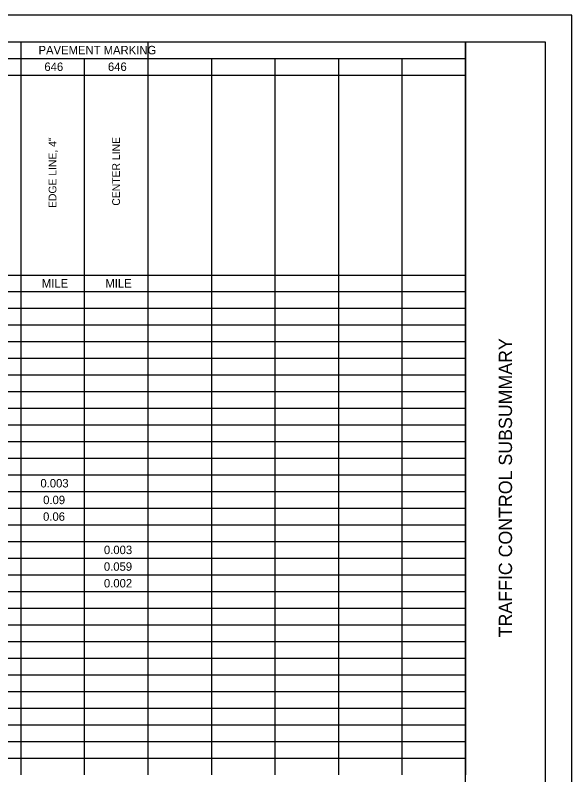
# Model space of a CAD drawing. Extents: x 0 to 34, y 0 to 22.
# Drawn here: x 23.52 to 34, y 7.71 to 22 of the extents above; entities that cross this region are included whole.
import ezdxf

# ---------------------------------------------------------------- set-up
doc = ezdxf.new("R2010")
doc.units = 0
for name, color, linetype in [('SH_Border', 7, 'Continuous'), ('SH_Cut_Line', 7, 'Continuous'), ('SH_Data', 7, 'Continuous'), ('SH_Text', 7, 'Continuous')]:
    doc.layers.add(name, color=color, linetype=linetype)

msp = doc.modelspace()

# ---------------------------------------------------------------- linework, layer by layer
at = {"layer": 'SH_Border'}
msp.add_line((32, 0.5), (32, 21.5), dxfattribs=at)
msp.add_lwpolyline([(1.5, 21.5), (33.5, 21.5), (33.5, 0.5), (1.5, 0.5)], close=True, dxfattribs=at)
at = {"layer": 'SH_Cut_Line'}
msp.add_lwpolyline([(0, 0), (34, 0), (34, 22), (0, 22)], close=True, dxfattribs=at)
at = {"layer": 'SH_Text'}
for p, q in [((16.454, 21.5), (23.629, 21.5)), ((23.629, 21.5), (24.825, 21.5)), ((23.629, 21.5), (23.629, 21.187)), ((24.825, 21.5), (26.021, 21.5)), ((26.021, 21.5), (28.413, 21.5)), ((26.021, 21.5), (26.021, 21.187)), ((28.413, 21.5), (30.804, 21.5)), ((30.804, 21.5), (32, 21.5)), ((32, 21.5), (32, 21.187)), ((16.454, 21.187), (23.629, 21.187)), ((23.629, 21.187), (24.825, 21.187)), ((23.629, 21.187), (23.629, 20.873)), ((24.825, 21.187), (26.021, 21.187)), ((24.825, 21.187), (24.825, 20.873)), ((26.021, 21.187), (28.413, 21.187)), ((26.021, 21.187), (26.021, 20.873)), ((27.217, 21.187), (27.217, 20.873)), ((28.413, 21.187), (30.804, 21.187)), ((28.413, 21.187), (28.413, 20.873)), ((29.608, 21.187), (29.608, 20.873)), ((30.804, 21.187), (32, 21.187)), ((30.804, 21.187), (30.804, 20.873)), ((32, 21.187), (32, 20.873)), ((16.454, 20.873), (23.629, 20.873)), ((23.629, 20.873), (24.825, 20.873)), ((23.629, 20.873), (23.629, 20.56)), ((24.825, 20.873), (26.021, 20.873)), ((24.825, 20.873), (24.825, 20.56)), ((26.021, 20.873), (28.413, 20.873)), ((26.021, 20.873), (26.021, 20.56)), ((27.217, 20.873), (27.217, 20.56)), ((28.413, 20.873), (30.804, 20.873)), ((28.413, 20.873), (28.413, 20.56)), ((29.608, 20.873), (29.608, 20.56)), ((30.804, 20.873), (32, 20.873)), ((30.804, 20.873), (30.804, 20.56)), ((32, 20.873), (32, 20.56)), ((23.629, 20.56), (23.629, 19.933)), ((24.825, 20.56), (24.825, 19.933)), ((26.021, 20.56), (26.021, 19.933)), ((27.217, 20.56), (27.217, 19.933)), ((28.413, 20.56), (28.413, 19.933)), ((29.608, 20.56), (29.608, 19.933)), ((30.804, 20.56), (30.804, 19.933)), ((32, 20.56), (32, 19.933)), ((23.629, 19.933), (23.629, 19.619)), ((24.825, 19.933), (24.825, 19.619)), ((26.021, 19.933), (26.021, 19.619)), ((27.217, 19.933), (27.217, 19.619)), ((28.413, 19.933), (28.413, 19.619)), ((29.608, 19.933), (29.608, 19.619)), ((30.804, 19.933), (30.804, 19.619)), ((32, 19.933), (32, 19.619)), ((23.629, 19.619), (23.629, 19.306)), ((24.825, 19.619), (24.825, 19.306)), ((26.021, 19.619), (26.021, 19.306)), ((27.217, 19.619), (27.217, 19.306)), ((28.413, 19.619), (28.413, 19.306)), ((29.608, 19.619), (29.608, 19.306)), ((30.804, 19.619), (30.804, 19.306)), ((32, 19.619), (32, 19.306)), ((23.629, 19.306), (23.629, 18.993)), ((24.825, 19.306), (24.825, 18.993)), ((26.021, 19.306), (26.021, 18.993)), ((27.217, 19.306), (27.217, 18.993)), ((28.413, 19.306), (28.413, 18.993)), ((29.608, 19.306), (29.608, 18.993)), ((30.804, 19.306), (30.804, 18.993)), ((32, 19.306), (32, 18.993)), ((23.629, 18.993), (23.629, 18.679)), ((24.825, 18.993), (24.825, 18.679)), ((26.021, 18.993), (26.021, 18.679)), ((27.217, 18.993), (27.217, 18.679)), ((28.413, 18.993), (28.413, 18.679)), ((29.608, 18.993), (29.608, 18.679)), ((30.804, 18.993), (30.804, 18.679)), ((32, 18.993), (32, 18.679)), ((23.629, 18.679), (23.629, 18.366)), ((24.825, 18.679), (24.825, 18.366)), ((26.021, 18.679), (26.021, 18.366)), ((27.217, 18.679), (27.217, 18.366)), ((28.413, 18.679), (28.413, 18.366)), ((29.608, 18.679), (29.608, 18.366)), ((30.804, 18.679), (30.804, 18.366)), ((32, 18.679), (32, 18.366)), ((23.629, 18.366), (23.629, 18.052)), ((24.825, 18.366), (24.825, 18.052)), ((26.021, 18.366), (26.021, 18.052)), ((27.217, 18.366), (27.217, 18.052)), ((28.413, 18.366), (28.413, 18.052)), ((29.608, 18.366), (29.608, 18.052)), ((30.804, 18.366), (30.804, 18.052)), ((32, 18.366), (32, 18.052)), ((23.629, 18.052), (23.629, 17.739)), ((24.825, 18.052), (24.825, 17.739)), ((26.021, 18.052), (26.021, 17.739)), ((27.217, 18.052), (27.217, 17.739)), ((28.413, 18.052), (28.413, 17.739)), ((29.608, 18.052), (29.608, 17.739)), ((30.804, 18.052), (30.804, 17.739)), ((32, 18.052), (32, 17.739)), ((23.629, 17.739), (23.629, 17.425)), ((24.825, 17.739), (24.825, 17.425)), ((26.021, 17.739), (26.021, 17.425)), ((27.217, 17.739), (27.217, 17.425)), ((28.413, 17.739), (28.413, 17.425)), ((29.608, 17.739), (29.608, 17.425)), ((30.804, 17.739), (30.804, 17.425)), ((32, 17.739), (32, 17.425)), ((23.629, 17.425), (23.629, 16.799)), ((24.825, 17.425), (24.825, 16.799)), ((26.021, 17.425), (26.021, 16.799)), ((27.217, 17.425), (27.217, 16.799)), ((28.413, 17.425), (28.413, 16.799)), ((29.608, 17.425), (29.608, 16.799)), ((30.804, 17.425), (30.804, 16.799)), ((32, 17.425), (32, 16.799)), ((16.454, 17.112), (23.629, 17.112)), ((23.629, 17.112), (24.825, 17.112)), ((24.825, 17.112), (26.021, 17.112)), ((26.021, 17.112), (28.413, 17.112)), ((28.413, 17.112), (30.804, 17.112)), ((30.804, 17.112), (32, 17.112)), ((16.454, 16.799), (23.629, 16.799)), ((23.629, 16.799), (24.825, 16.799)), ((23.629, 16.799), (23.629, 16.485)), ((24.825, 16.799), (26.021, 16.799)), ((24.825, 16.799), (24.825, 16.485)), ((26.021, 16.799), (28.413, 16.799)), ((26.021, 16.799), (26.021, 16.485)), ((27.217, 16.799), (27.217, 16.485)), ((28.413, 16.799), (30.804, 16.799)), ((28.413, 16.799), (28.413, 16.485)), ((29.608, 16.799), (29.608, 16.485)), ((30.804, 16.799), (32, 16.799)), ((30.804, 16.799), (30.804, 16.485)), ((32, 16.799), (32, 16.485)), ((16.454, 16.485), (23.629, 16.485)), ((23.629, 16.485), (24.825, 16.485)), ((23.629, 16.485), (23.629, 15.231)), ((24.825, 16.485), (26.021, 16.485)), ((24.825, 16.485), (24.825, 15.231)), ((26.021, 16.485), (28.413, 16.485)), ((26.021, 16.485), (26.021, 15.231)), ((27.217, 16.485), (27.217, 15.231)), ((28.413, 16.485), (30.804, 16.485)), ((28.413, 16.485), (28.413, 15.231)), ((29.608, 16.485), (29.608, 15.231)), ((30.804, 16.485), (32, 16.485)), ((30.804, 16.485), (30.804, 15.231)), ((32, 16.485), (32, 15.231)), ((16.454, 16.172), (23.629, 16.172)), ((23.629, 16.172), (24.825, 16.172)), ((24.825, 16.172), (26.021, 16.172)), ((26.021, 16.172), (28.413, 16.172)), ((28.413, 16.172), (30.804, 16.172)), ((30.804, 16.172), (32, 16.172)), ((16.454, 15.858), (23.629, 15.858)), ((23.629, 15.858), (24.825, 15.858)), ((24.825, 15.858), (26.021, 15.858)), ((26.021, 15.858), (28.413, 15.858)), ((28.413, 15.858), (30.804, 15.858)), ((30.804, 15.858), (32, 15.858)), ((16.454, 15.545), (23.629, 15.545)), ((23.629, 15.545), (24.825, 15.545)), ((24.825, 15.545), (26.021, 15.545)), ((26.021, 15.545), (28.413, 15.545)), ((28.413, 15.545), (30.804, 15.545)), ((30.804, 15.545), (32, 15.545)), ((16.454, 15.231), (23.629, 15.231)), ((23.629, 15.231), (24.825, 15.231)), ((23.629, 15.231), (23.629, 14.291)), ((24.825, 15.231), (26.021, 15.231)), ((24.825, 15.231), (24.825, 14.291)), ((26.021, 15.231), (28.413, 15.231)), ((26.021, 15.231), (26.021, 14.291)), ((27.217, 15.231), (27.217, 14.291)), ((28.413, 15.231), (30.804, 15.231)), ((28.413, 15.231), (28.413, 14.291)), ((29.608, 15.231), (29.608, 14.291)), ((30.804, 15.231), (32, 15.231)), ((30.804, 15.231), (30.804, 14.291)), ((32, 15.231), (32, 14.291)), ((16.454, 14.918), (23.629, 14.918)), ((23.629, 14.918), (24.825, 14.918)), ((24.825, 14.918), (26.021, 14.918)), ((26.021, 14.918), (28.413, 14.918)), ((28.413, 14.918), (30.804, 14.918)), ((30.804, 14.918), (32, 14.918)), ((16.454, 14.604), (23.629, 14.604)), ((23.629, 14.604), (24.825, 14.604)), ((24.825, 14.604), (26.021, 14.604)), ((26.021, 14.604), (28.413, 14.604)), ((28.413, 14.604), (30.804, 14.604)), ((30.804, 14.604), (32, 14.604)), ((16.454, 14.291), (23.629, 14.291)), ((23.629, 14.291), (24.825, 14.291)), ((23.629, 14.291), (23.629, 13.664)), ((24.825, 14.291), (26.021, 14.291)), ((24.825, 14.291), (24.825, 13.664)), ((26.021, 14.291), (28.413, 14.291)), ((26.021, 14.291), (26.021, 13.664)), ((27.217, 14.291), (27.217, 13.664)), ((28.413, 14.291), (30.804, 14.291)), ((28.413, 14.291), (28.413, 13.664)), ((29.608, 14.291), (29.608, 13.664)), ((30.804, 14.291), (32, 14.291)), ((30.804, 14.291), (30.804, 13.664)), ((32, 14.291), (32, 13.664)), ((16.454, 13.978), (23.629, 13.978)), ((23.629, 13.978), (24.825, 13.978)), ((24.825, 13.978), (26.021, 13.978)), ((26.021, 13.978), (28.413, 13.978)), ((28.413, 13.978), (30.804, 13.978)), ((30.804, 13.978), (32, 13.978)), ((16.454, 13.664), (23.629, 13.664)), ((23.629, 13.664), (24.825, 13.664)), ((23.629, 13.664), (23.629, 13.351)), ((24.825, 13.664), (26.021, 13.664)), ((24.825, 13.664), (24.825, 13.351)), ((26.021, 13.664), (28.413, 13.664)), ((26.021, 13.664), (26.021, 13.351)), ((27.217, 13.664), (27.217, 13.351)), ((28.413, 13.664), (30.804, 13.664)), ((28.413, 13.664), (28.413, 13.351)), ((29.608, 13.664), (29.608, 13.351)), ((30.804, 13.664), (32, 13.664)), ((30.804, 13.664), (30.804, 13.351)), ((32, 13.664), (32, 13.351)), ((16.454, 13.351), (23.629, 13.351)), ((23.629, 13.351), (24.825, 13.351)), ((23.629, 13.351), (23.629, 13.037)), ((24.825, 13.351), (26.021, 13.351)), ((24.825, 13.351), (24.825, 13.037)), ((26.021, 13.351), (28.413, 13.351)), ((26.021, 13.351), (26.021, 13.037)), ((27.217, 13.351), (27.217, 13.037)), ((28.413, 13.351), (30.804, 13.351)), ((28.413, 13.351), (28.413, 13.037)), ((29.608, 13.351), (29.608, 13.037)), ((30.804, 13.351), (32, 13.351)), ((30.804, 13.351), (30.804, 13.037)), ((32, 13.351), (32, 13.037)), ((16.454, 13.037), (23.629, 13.037)), ((23.629, 13.037), (24.825, 13.037)), ((23.629, 13.037), (23.629, 12.41)), ((24.825, 13.037), (26.021, 13.037)), ((24.825, 13.037), (24.825, 12.41)), ((26.021, 13.037), (28.413, 13.037)), ((26.021, 13.037), (26.021, 12.41)), ((27.217, 13.037), (27.217, 12.41)), ((28.413, 13.037), (30.804, 13.037)), ((28.413, 13.037), (28.413, 12.41)), ((29.608, 13.037), (29.608, 12.41)), ((30.804, 13.037), (32, 13.037)), ((30.804, 13.037), (30.804, 12.41)), ((32, 13.037), (32, 12.41)), ((16.454, 12.724), (23.629, 12.724)), ((23.629, 12.724), (24.825, 12.724)), ((24.825, 12.724), (26.021, 12.724)), ((26.021, 12.724), (28.413, 12.724)), ((28.413, 12.724), (30.804, 12.724)), ((30.804, 12.724), (32, 12.724)), ((16.454, 12.41), (23.629, 12.41)), ((23.629, 12.41), (24.825, 12.41)), ((23.629, 12.41), (23.629, 11.47)), ((24.825, 12.41), (26.021, 12.41)), ((24.825, 12.41), (24.825, 11.47)), ((26.021, 12.41), (28.413, 12.41)), ((26.021, 12.41), (26.021, 11.47)), ((27.217, 12.41), (27.217, 11.47)), ((28.413, 12.41), (30.804, 12.41)), ((28.413, 12.41), (28.413, 11.47)), ((29.608, 12.41), (29.608, 11.47)), ((30.804, 12.41), (32, 12.41)), ((30.804, 12.41), (30.804, 11.47)), ((32, 12.41), (32, 11.47)), ((16.454, 12.097), (23.629, 12.097)), ((23.629, 12.097), (24.825, 12.097)), ((24.825, 12.097), (26.021, 12.097)), ((26.021, 12.097), (28.413, 12.097)), ((28.413, 12.097), (30.804, 12.097)), ((30.804, 12.097), (32, 12.097)), ((16.454, 11.784), (23.629, 11.784)), ((23.629, 11.784), (24.825, 11.784)), ((24.825, 11.784), (26.021, 11.784)), ((26.021, 11.784), (28.413, 11.784)), ((28.413, 11.784), (30.804, 11.784)), ((30.804, 11.784), (32, 11.784)), ((16.454, 11.47), (23.629, 11.47)), ((23.629, 11.47), (24.825, 11.47)), ((23.629, 11.47), (23.629, 10.843)), ((24.825, 11.47), (26.021, 11.47)), ((24.825, 11.47), (24.825, 10.843)), ((26.021, 11.47), (28.413, 11.47)), ((26.021, 11.47), (26.021, 10.843)), ((27.217, 11.47), (27.217, 10.843)), ((28.413, 11.47), (30.804, 11.47)), ((28.413, 11.47), (28.413, 10.843)), ((29.608, 11.47), (29.608, 10.843)), ((30.804, 11.47), (32, 11.47)), ((30.804, 11.47), (30.804, 10.843)), ((32, 11.47), (32, 10.843)), ((16.454, 11.157), (23.629, 11.157)), ((23.629, 11.157), (24.825, 11.157)), ((24.825, 11.157), (26.021, 11.157)), ((26.021, 11.157), (28.413, 11.157)), ((28.413, 11.157), (30.804, 11.157)), ((30.804, 11.157), (32, 11.157)), ((16.454, 10.843), (23.629, 10.843)), ((23.629, 10.843), (24.825, 10.843)), ((23.629, 10.843), (23.629, 9.903)), ((24.825, 10.843), (26.021, 10.843)), ((24.825, 10.843), (24.825, 9.903)), ((26.021, 10.843), (28.413, 10.843)), ((26.021, 10.843), (26.021, 9.903)), ((27.217, 10.843), (27.217, 9.903)), ((28.413, 10.843), (30.804, 10.843)), ((28.413, 10.843), (28.413, 9.903)), ((29.608, 10.843), (29.608, 9.903)), ((30.804, 10.843), (32, 10.843)), ((30.804, 10.843), (30.804, 9.903)), ((32, 10.843), (32, 9.903)), ((16.454, 10.53), (23.629, 10.53)), ((23.629, 10.53), (24.825, 10.53)), ((24.825, 10.53), (26.021, 10.53)), ((26.021, 10.53), (28.413, 10.53)), ((28.413, 10.53), (30.804, 10.53)), ((30.804, 10.53), (32, 10.53)), ((16.454, 10.216), (23.629, 10.216)), ((23.629, 10.216), (24.825, 10.216)), ((24.825, 10.216), (26.021, 10.216)), ((26.021, 10.216), (28.413, 10.216)), ((28.413, 10.216), (30.804, 10.216)), ((30.804, 10.216), (32, 10.216)), ((16.454, 9.903), (23.629, 9.903)), ((23.629, 9.903), (24.825, 9.903)), ((23.629, 9.903), (23.629, 9.276)), ((24.825, 9.903), (26.021, 9.903)), ((24.825, 9.903), (24.825, 9.276)), ((26.021, 9.903), (28.413, 9.903)), ((26.021, 9.903), (26.021, 9.276)), ((27.217, 9.903), (27.217, 9.276)), ((28.413, 9.903), (30.804, 9.903)), ((28.413, 9.903), (28.413, 9.276)), ((29.608, 9.903), (29.608, 9.276)), ((30.804, 9.903), (32, 9.903)), ((30.804, 9.903), (30.804, 9.276)), ((32, 9.903), (32, 9.276)), ((16.454, 9.59), (23.629, 9.59)), ((23.629, 9.59), (24.825, 9.59)), ((24.825, 9.59), (26.021, 9.59)), ((26.021, 9.59), (28.413, 9.59)), ((28.413, 9.59), (30.804, 9.59)), ((30.804, 9.59), (32, 9.59)), ((16.454, 9.276), (23.629, 9.276)), ((23.629, 9.276), (24.825, 9.276)), ((23.629, 9.276), (23.629, 8.336)), ((24.825, 9.276), (26.021, 9.276)), ((24.825, 9.276), (24.825, 8.336)), ((26.021, 9.276), (28.413, 9.276)), ((26.021, 9.276), (26.021, 8.336)), ((27.217, 9.276), (27.217, 8.336)), ((28.413, 9.276), (30.804, 9.276)), ((28.413, 9.276), (28.413, 8.336)), ((29.608, 9.276), (29.608, 8.336)), ((30.804, 9.276), (32, 9.276)), ((30.804, 9.276), (30.804, 8.336)), ((32, 9.276), (32, 8.336)), ((16.454, 8.963), (23.629, 8.963)), ((23.629, 8.963), (24.825, 8.963)), ((24.825, 8.963), (26.021, 8.963)), ((26.021, 8.963), (28.413, 8.963)), ((28.413, 8.963), (30.804, 8.963)), ((30.804, 8.963), (32, 8.963)), ((16.454, 8.649), (23.629, 8.649)), ((23.629, 8.649), (24.825, 8.649)), ((24.825, 8.649), (26.021, 8.649)), ((26.021, 8.649), (28.413, 8.649)), ((28.413, 8.649), (30.804, 8.649)), ((30.804, 8.649), (32, 8.649)), ((16.454, 8.336), (23.629, 8.336)), ((23.629, 8.336), (24.825, 8.336)), ((23.629, 8.336), (23.629, 7.709)), ((24.825, 8.336), (26.021, 8.336)), ((24.825, 8.336), (24.825, 7.709)), ((26.021, 8.336), (28.413, 8.336)), ((26.021, 8.336), (26.021, 7.709)), ((27.217, 8.336), (27.217, 7.709)), ((28.413, 8.336), (30.804, 8.336)), ((28.413, 8.336), (28.413, 7.709)), ((29.608, 8.336), (29.608, 7.709)), ((30.804, 8.336), (32, 8.336)), ((30.804, 8.336), (30.804, 7.709)), ((32, 8.336), (32, 7.709)), ((16.454, 8.022), (23.629, 8.022)), ((23.629, 8.022), (24.825, 8.022)), ((24.825, 8.022), (26.021, 8.022)), ((26.021, 8.022), (28.413, 8.022)), ((28.413, 8.022), (30.804, 8.022)), ((30.804, 8.022), (32, 8.022))]:
    msp.add_line(p, q, dxfattribs=at)

# ---------------------------------------------------------------- texts
at = {"layer": 'SH_Data'}
msp.add_text('TRAFFIC CONTROL SUBSUMMARY', height=0.25, rotation=90, dxfattribs=at).set_placement((32.875, 10.295))
at = {"layer": 'SH_Text'}
for s, height, p in [('PAVEMENT MARKING', 0.15858, (23.964, 21.264)), ('646', 0.1586, (24.074, 20.951)), ('646', 0.1586, (25.27, 20.951)), ('MILE', 0.1586, (24.026, 16.876)), ('MILE', 0.1586, (25.222, 16.876)), ('0.003', 0.1586, (23.999, 13.115)), ('0.09', 0.1586, (24.051, 12.801)), ('0.06', 0.1586, (24.049, 12.488)), ('0.003', 0.1586, (25.195, 11.861)), ('0.059', 0.1586, (25.194, 11.548)), ('0.002', 0.1586, (25.195, 11.234))]:
    msp.add_text(s, height=height, dxfattribs=at).set_placement(p)
for s, p in [('EDGE LINE, 4"', (24.3, 18.373)), ('CENTER LINE', (25.496, 18.416))]:
    msp.add_text(s, height=0.14604, rotation=90, dxfattribs=at).set_placement(p)

doc.saveas('drawing.dxf')
